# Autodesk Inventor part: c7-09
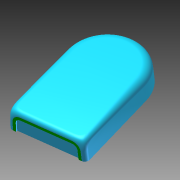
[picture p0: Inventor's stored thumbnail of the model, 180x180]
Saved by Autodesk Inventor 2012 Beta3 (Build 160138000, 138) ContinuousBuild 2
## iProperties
Created: 2010-12
Part Number: c7-09
Material: Default
Document SubType Name: Modeling
Designer: Beta-8540w
Density: 1 g/cm^3
Author: Beta-8540w
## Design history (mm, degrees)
sketch "Sketch1"
  geometry: L1 (-25, 0)-(25, 0); L2 (25, 0)-(25, 80); L3 (25, 80)-(-25, 80); L4 (-25, 80)-(-25, 0); 2 further points
  constraints: 8 end point, 2 parallel, 1 coincident, 1 horizontal, 1 midpoint, 1 perpendicular
  dimensions: "d0" = 50 distance of L3.end L2.end; "d1" = 80 distance of L2.end L1.end
extrude "Extrusion1" new body sketch "Sketch1" distance "d2" = 15; taper "d3" = 0 deg
feature "FaceDraft1" dims angle "d4" = -2 deg
fillet "Fillet1"
fillet "Fillet2" dims "d5" = 8, "d6" = 8, "d7" = 8, "d8" = 8, "d9" = 8, "d10" = 8, "d11" = 3, "d12" = 3, "d13" = 3, "d14" = 6, "d15" = 5
sketch "Sketch2"
  geometry: L1 (5.522, 12)-(38.474, 12) reference; L2 (0, 0)-(43.996, 0) reference; L3 (41.757, 6.83)-(41.995, 0); L4 (41.925, 2)-(2.071, 2); L5 (2.001, 0)-(2.24, 6.83); L6 (5.522, 10)-(38.474, 10); A1 r 5.284 centre (38.474, 6.716) between (43.755, 6.9) and (38.474, 12) reference; A2 r 5.284 centre (5.522, 6.716) between (5.522, 12) and (0.241, 6.9) reference; A3 r 3.284 centre (38.474, 6.716) between (41.757, 6.83) and (38.474, 10); A4 r 3.284 centre (5.522, 6.716) between (5.522, 10) and (2.24, 6.83); 1 further point
  constraints: 8 end point, 4 point on circle, 4 point on line, 2 centre point, 1 other
  dimensions: "d16" = 2 radial gap between concentric circles of A2 A4
extrude "Extrusion2" cut sketch "Sketch2" distance "d17" = 1; taper "d18" = 0 deg
body "Solid1"
